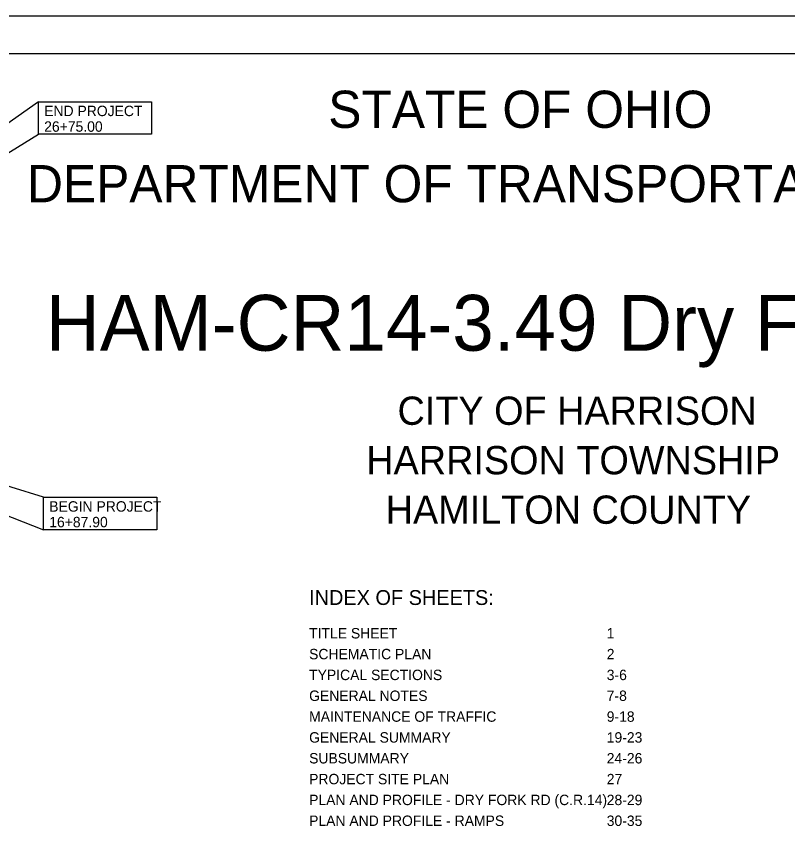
# Model space of a CAD drawing. Extents: x -7.5 to 26.5, y 3.5 to 25.5.
# Drawn here: x 2.14 to 12.51, y 14.57 to 25.5 of the extents above; entities that cross this region are included whole.
import ezdxf

# ---------------------------------------------------------------- set-up
doc = ezdxf.new("R2010")
doc.units = 0
for name, color, linetype in [('SH_Border', 7, 'Continuous'), ('SH_Cut_Line', 7, 'Continuous'), ('SH_Text', 7, 'Continuous')]:
    doc.layers.add(name, color=color, linetype=linetype)

msp = doc.modelspace()

# ---------------------------------------------------------------- linework, layer by layer
at = {"layer": 'SH_Border'}
msp.add_lwpolyline([(-5.957, 25), (26.043, 25), (26.043, 4), (-5.957, 4)], close=True, dxfattribs=at)
at = {"layer": 'SH_Cut_Line'}
msp.add_lwpolyline([(-7.457, 3.5), (26.543, 3.5), (26.543, 25.5), (-7.457, 25.5)], close=True, dxfattribs=at)
at = {"layer": 'SH_Text'}
for points in [[(2.445, 24.351), (-2.596, 20.799), (2.445, 23.916)], [(2.445, 24.351), (3.963, 24.351), (3.963, 23.916), (2.445, 23.916)], [(2.513, 19.035), (-2.707, 20.65), (2.513, 18.6)], [(2.513, 19.035), (4.032, 19.035), (4.032, 18.6), (2.513, 18.6)]]:
    msp.add_lwpolyline(points, close=True, dxfattribs=at)

# ---------------------------------------------------------------- texts
for s, height, p in [('STATE OF OHIO', 0.5, (6.338, 24)), ('END PROJECT', 0.14, (2.52, 24.158)), ('26+75.00', 0.14, (2.52, 23.948)), ('DEPARTMENT OF TRANSPORTATION', 0.5, (2.29, 23)), ('HAM-CR14-3.49 Dry Fork Rd', 0.75, (2.544, 21.005)), ('CITY OF HARRISON', 0.38, (7.269, 20.009)), ('HARRISON TOWNSHIP', 0.38, (6.849, 19.344)), ('HAMILTON COUNTY', 0.38, (7.11, 18.679)), ('BEGIN PROJECT', 0.14, (2.588, 18.842)), ('16+87.90', 0.14, (2.588, 18.632)), ('INDEX OF SHEETS:', 0.2, (6.081, 17.588)), ('TITLE SHEET', 0.14, (6.081, 17.138)), ('1', 0.14, (10.081, 17.138)), ('SCHEMATIC PLAN', 0.14, (6.081, 16.858)), ('2', 0.14, (10.081, 16.858)), ('TYPICAL SECTIONS', 0.14, (6.081, 16.578)), ('3-6', 0.14, (10.081, 16.578)), ('GENERAL NOTES', 0.14, (6.081, 16.298)), ('7-8', 0.14, (10.081, 16.298)), ('MAINTENANCE OF TRAFFIC', 0.14, (6.081, 16.018)), ('9-18', 0.14, (10.081, 16.018)), ('GENERAL SUMMARY', 0.14, (6.081, 15.738)), ('19-23', 0.14, (10.081, 15.738)), ('SUBSUMMARY', 0.14, (6.081, 15.458)), ('24-26', 0.14, (10.081, 15.458)), ('PROJECT SITE PLAN', 0.14, (6.081, 15.178)), ('27', 0.14, (10.081, 15.178)), ('PLAN AND PROFILE - DRY FORK RD (C.R.14)', 0.14, (6.081, 14.898)), ('28-29', 0.14, (10.081, 14.898)), ('PLAN AND PROFILE - RAMPS', 0.14, (6.081, 14.618)), ('30-35', 0.14, (10.081, 14.618))]:
    msp.add_text(s, height=height, dxfattribs=at).set_placement(p)

doc.saveas('drawing.dxf')
